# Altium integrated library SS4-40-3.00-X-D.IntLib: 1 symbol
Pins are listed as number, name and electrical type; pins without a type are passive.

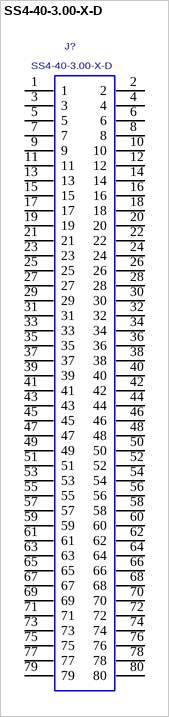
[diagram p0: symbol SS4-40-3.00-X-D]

## SS4-40-3.00-X-D
designator J?
0.4MM SOCKET STRIP ASSEMBLY, 80 PINS.; MANUFACTURER: SAMTEC
footprint SS4-40-3.00-X-D
pins: 1, 2, 3, 4, 5, 6, 7, 8, 9, 10, 11, 12, 13, 14, 15, 16, 17, 18, 19, 20, 21, 22, 23, 24, 25, 26, 27, 28, 29, 30, 31, 32, 33, 34, 35, 36, 37, 38, 39, 40, 41, 42, 43, 44, 45, 46, 47, 48, 49, 50, 51, 52, 53, 54, 55, 56, 57, 58, 59, 60, 61, 62, 63, 64, 65, 66, 67, 68, 69, 70, 71, 72, 73, 74, 75, 76, 77, 78, 79, 80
